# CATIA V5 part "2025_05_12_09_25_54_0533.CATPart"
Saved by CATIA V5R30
Part number: Zavesne_oko
Definition: 2025_05_12_09_25_54_0533
Nomenclature: 2025_05_12_09_25_54_0533
Source: Unknown
Description: PART-2025_05_12_09_25_54_0533-DESC
Bounding box of the stored display mesh (mm): x -30 to 30, y -15.25 to 15.25, z -19 to 93.99
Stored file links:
  E:\Bakalarka\Model\Forma_v7\2025_05_12_09_25_54_0533.CATPart
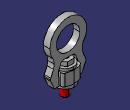
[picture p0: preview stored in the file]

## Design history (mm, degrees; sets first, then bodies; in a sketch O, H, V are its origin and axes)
Body1 "E1273_12" (main body)
  Solid1: solid without history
